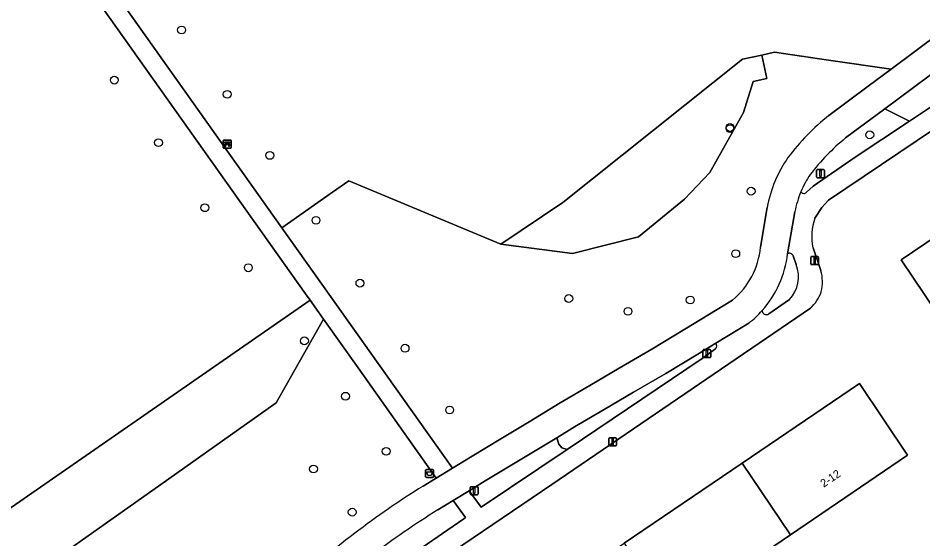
# Model space of a CAD drawing. Extents: x 157445 to 158888, y 383061 to 384688.
# Drawn here: x 157898.8 to 158011.8, y 383743.2 to 383808.2 of the extents above; entities that cross this region are included whole.
import ezdxf

# ---------------------------------------------------------------- set-up
doc = ezdxf.new("R2010")
doc.units = 0
for name, color, linetype in [('IMGEO_Afvalbak', 7, 'Continuous'), ('IMGEO_Bank', 7, 'Continuous'), ('IMGEO_Boom', 7, 'Continuous'), ('IMGEO_Erf', 7, 'Continuous'), ('IMGEO_Fietspad_gesloten', 7, 'Continuous'), ('IMGEO_Groenvoorziening', 7, 'Continuous'), ('IMGEO_Lichtmast', 7, 'Continuous'), ('IMGEO_Pand', 7, 'Continuous'), ('IMGEO_Pand_nummerreeks', 7, 'Continuous'), ('IMGEO_Voetpad_halfverhard', 7, 'Continuous')]:
    doc.layers.add(name, color=color, linetype=linetype)

msp = doc.modelspace()

# ---------------------------------------------------------------- linework, layer by layer
at = {"layer": 'IMGEO_Afvalbak'}
for p, q in [((157949.68, 383750.96), (157949.68, 383751.76)), ((157949.68, 383751.76), (157949.68, 383750.96)), ((157949.78, 383751.86), (157950.57, 383751.86)), ((157950.57, 383751.86), (157949.78, 383751.86)), ((157950.67, 383751.76), (157950.67, 383750.96)), ((157950.67, 383750.96), (157950.67, 383751.76)), ((157950.57, 383750.86), (157949.78, 383750.86)), ((157949.78, 383750.86), (157950.57, 383750.86))]:
    msp.add_line(p, q, dxfattribs=at)
msp.add_lwpolyline([(157949.82, 383751.57), (157950.52, 383751.57), (157950.37, 383751.1), (157949.97, 383751.1), (157949.82, 383751.57)], dxfattribs=at)
for centre, start, end in [((157949.78, 383751.76), 90, 180), ((157949.78, 383751.76), 90, 180), ((157950.57, 383751.76), 0, 90), ((157950.57, 383751.76), 360, 90), ((157949.78, 383750.96), 180, 270), ((157949.78, 383750.96), 180, 270), ((157950.57, 383750.96), 270, 0), ((157950.57, 383750.96), 270, 0)]:
    msp.add_arc(centre, 0.1, start, end, dxfattribs=at)
at = {"layer": 'IMGEO_Bank'}
for p, q in [((157924.41, 383792.04), (157924.41, 383792.88)), ((157924.41, 383792.88), (157924.41, 383792.04)), ((157924.48, 383792.97), (157925.32, 383792.97)), ((157925.32, 383792.97), (157924.48, 383792.97)), ((157925.4, 383792.89), (157925.4, 383792.05)), ((157925.4, 383792.05), (157925.4, 383792.89)), ((157925.33, 383791.97), (157924.49, 383791.97)), ((157924.49, 383791.97), (157925.33, 383791.97)), ((157924.71, 383792.47), (157924.71, 383792.58)), ((157925.1, 383792.36), (157924.71, 383792.36)), ((157925.05, 383792.58), (157924.76, 383792.58)), ((157924.76, 383792.58), (157924.76, 383792.47)), ((157924.76, 383792.47), (157925.05, 383792.47)), ((157925.05, 383792.47), (157925.05, 383792.58)), ((157925.1, 383792.58), (157925.1, 383792.47))]:
    msp.add_line(p, q, dxfattribs=at)
for points in [[(157924.65, 383792.36), (157924.51, 383792.36), (157924.62, 383792.47), (157924.71, 383792.47)], [(157924.71, 383792.58), (157924.62, 383792.58), (157924.62, 383792.75), (157925.19, 383792.75), (157925.19, 383792.58), (157925.1, 383792.58)], [(157924.7, 383792.36), (157924.7, 383792.15), (157924.66, 383792.15), (157924.66, 383792.36)], [(157925.1, 383792.47), (157925.19, 383792.47), (157925.3, 383792.36), (157925.16, 383792.36)], [(157925.15, 383792.36), (157925.15, 383792.15), (157925.11, 383792.15), (157925.11, 383792.36)]]:
    msp.add_lwpolyline(points, dxfattribs=at)
for centre, radius, start, end in [((157924.48, 383792.89), 0.0779, 92.4484, 184.2845), ((157924.48, 383792.89), 0.0779, 92.4484, 184.2845), ((157925.33, 383792.89), 0.0779, 2.4484, 94.2845), ((157925.33, 383792.89), 0.0779, 2.4484, 94.2845), ((157924.48, 383792.04), 0.0779, 182.4484, 274.2845), ((157924.48, 383792.04), 0.0779, 182.4484, 274.2845), ((157924.65, 383792.36), 0.00671, 2.8957, 87.1043), ((157924.71, 383792.36), 0.00671, 92.8957, 177.1043), ((157924.71, 383792.58), 0.00671, 2.8957, 87.1043), ((157924.71, 383792.47), 0.00671, 272.8957, 357.1043), ((157924.76, 383792.58), 0.00671, 92.8957, 177.1043), ((157924.76, 383792.47), 0.00671, 182.8957, 267.1043), ((157925.05, 383792.58), 0.00671, 2.8957, 87.1043), ((157925.05, 383792.47), 0.00671, 272.8957, 357.1043), ((157925.1, 383792.58), 0.00671, 92.8957, 177.1043), ((157925.1, 383792.47), 0.00671, 182.8957, 267.1043), ((157925.1, 383792.36), 0.00671, 2.8957, 87.1043), ((157925.16, 383792.36), 0.00671, 92.8957, 177.1043), ((157925.33, 383792.04), 0.0779, 272.4484, 4.2845), ((157925.33, 383792.04), 0.0779, 272.4484, 4.2845)]:
    msp.add_arc(centre, radius, start, end, dxfattribs=at)
at = {"layer": 'IMGEO_Boom'}
for centre in [(157919.2, 383806.7), (157910.8, 383800.44), (157924.9, 383798.67), (157987.69, 383794.53), (157987.69, 383794.39), (158005.14, 383793.61), (157916.31, 383792.64), (157930.22, 383791.05), (157990.32, 383786.58), (157922.11, 383784.52), (157935.98, 383782.95), (157988.4, 383778.79), (157927.53, 383777.03), (157941.47, 383775.11), (157967.55, 383773.19), (157982.72, 383773.01), (157974.94, 383771.59), (157934.54, 383767.91), (157947.11, 383766.99), (157939.67, 383761), (157952.68, 383759.29), (157944.75, 383754.13), (157935.67, 383751.93), (157940.51, 383746.54)]:
    msp.add_circle(centre, 0.489, dxfattribs=at)
at = {"layer": 'IMGEO_Erf'}
for points in [[(158015.06, 383769.11), (158009.05, 383778.04), (158023.72, 383787.93), (158038.43, 383797.85), (158053.11, 383807.74), (158059.13, 383798.82), (158044.45, 383788.92), (158029.74, 383779.01)], [(157965.89, 383723.81), (157959.82, 383732.77), (157974.48, 383742.69), (157989.2, 383752.66), (158003.86, 383762.58), (158009.87, 383753.66), (157995.23, 383743.72), (157980.54, 383733.75)]]:
    msp.add_lwpolyline(points, close=True, dxfattribs=at)
for points in [[(158024.3, 383801.81), (158000, 383785.45), (157999.15, 383784.53), (157998.29, 383783.2)], [(157998.05, 383779.53), (157999.04, 383776.67)], [(157997.72, 383771.99), (157965.42, 383750), (157950.71, 383739.99)]]:
    msp.add_lwpolyline(points, dxfattribs=at)
for centre, radius, start, end in [((158004.36, 383780.95), 6.47, 159.6574, 192.6688), ((157994.01, 383775.27), 5.22, 346.2888, 15.4975), ((157994.39, 383775.66), 4.96, 312.2197, 340.8918)]:
    msp.add_arc(centre, radius, start, end, dxfattribs=at)
at = {"layer": 'IMGEO_Fietspad_gesloten'}
for points in [[(158013.89, 383806.34), (158007.8, 383801.81), (158004.92, 383799.67), (158000.03, 383796.04)], [(158002.12, 383793.23), (158007.01, 383796.86), (158015.98, 383803.53)], [(157992.33, 383784.57), (157991.51, 383779.59)], [(157994.88, 383778.78), (157995.78, 383784.01)], [(157988.01, 383772.99), (157982.06, 383769.35), (157977.92, 383766.87), (157973.86, 383764.52), (157970.19, 383762.35), (157966.48, 383760.17), (157962.59, 383757.82), (157959.05, 383755.7), (157955.29, 383753.42), (157953.02, 383752.04), (157950.98, 383750.79), (157949.35, 383749.79)], [(157951.19, 383746.81), (157953.12, 383747.99), (157955.1, 383749.2), (157957.11, 383750.43), (157960.86, 383752.7), (157964.4, 383754.82), (157966.06, 383755.83), (157968.27, 383757.17), (157971.97, 383759.34), (157975.62, 383761.5), (157979.69, 383763.85), (157983.88, 383766.36), (157985.93, 383767.62), (157990.04, 383770.13)]]:
    msp.add_lwpolyline(points, dxfattribs=at)
for centre, radius, start, end in [((158018.86, 383772.59), 30.07, 128.7726, 142.785), ((158018.94, 383772.55), 26.65, 129.132, 142.82), ((158008.1, 383781.64), 16.04, 145.2695, 169.4764), ((158008.14, 383781.62), 12.59, 145.9866, 157.1941), ((158008.92, 383781.39), 13.4, 157.5985, 168.7371), ((157981.65, 383780.6), 9.91, 309.8678, 354.1487), ((157982.13, 383780.24), 12.83, 318.2123, 353.4888), ((157982.23, 383780.12), 12.68, 308.0057, 318.283), ((158002.15, 383664.27), 100.5, 121.6925, 127.5948), ((158002, 383664.49), 96.74, 121.6856, 127.6039), ((158010.5, 383651.88), 115.42, 127.1273, 132.8541)]:
    msp.add_arc(centre, radius, start, end, dxfattribs=at)
at = {"layer": 'IMGEO_Groenvoorziening'}
for points in [[(157947.81, 383908.45), (157904.24, 383852.49), (157897.07, 383843.39), (157895.49, 383841.38), (157893.13, 383838.5), (157893.58, 383835.72), (157894.56, 383834.4), (157906.36, 383817.74), (157931.74, 383782.01), (157938.04, 383786.45), (157940.08, 383787.89), (157959.05, 383779.97), (157966.82, 383785.16), (157989.25, 383803.05), (157991.64, 383803.57), (157993.23, 383803.91), (158000, 383802.93), (158007.8, 383801.81), (158013.89, 383806.34)], [(157874.04, 383842.42), (157871.01, 383843.07), (157845.04, 383847.43), (157846.95, 383865.51), (157846.51, 383865.55), (157845.36, 383867.13), (157844.48, 383869.82), (157844.01, 383877.86), (157841.91, 383862.89), (157840.6, 383852.7), (157835.43, 383801.71), (157833.4, 383784.91), (157830.98, 383767.08), (157846.43, 383747.46), (157867.23, 383761.67), (157884.44, 383737.79), (157935.24, 383772.99), (157934.69, 383773.78), (157900.3, 383822.21)], [(158000.03, 383796.04), (158004.92, 383799.67), (158007.8, 383801.81), (158000, 383802.93), (157993.23, 383803.91), (157991.64, 383803.57), (157992.27, 383800.63), (157990.57, 383800.27), (157989.36, 383796.4), (157985.18, 383788.91), (157982.02, 383785.6), (157976.24, 383780.91), (157968.01, 383778.81), (157959.05, 383779.97), (157940.08, 383787.89), (157938.04, 383786.45), (157931.74, 383782.01), (157953.02, 383752.04), (157955.29, 383753.42), (157959.05, 383755.7), (157962.59, 383757.82), (157966.48, 383760.17), (157970.19, 383762.35), (157973.86, 383764.52), (157977.92, 383766.87), (157982.06, 383769.35), (157988.01, 383772.99)], [(158015.98, 383803.53), (158007.01, 383796.86), (158010.08, 383795.31), (158017.73, 383800.38), (158020.24, 383802.04)], [(158010.08, 383795.31), (158007.01, 383796.86), (158002.12, 383793.23)], [(157997.24, 383786.47), (157998.08, 383787.23), (158003.3, 383790.82), (158010.08, 383795.31)], [(157991.51, 383779.59), (157992.33, 383784.57)], [(157995.95, 383777.43), (157995.56, 383778.54)], [(157839.99, 383696.7), (157885.52, 383728.99), (157898.79, 383709.99), (157901.95, 383712.88), (157889.49, 383730.85), (157916.62, 383750), (157931.02, 383760.17), (157936.92, 383770.63), (157935.24, 383772.99), (157884.44, 383737.79), (157867.23, 383761.67), (157846.43, 383747.46), (157844.87, 383746.4), (157827.34, 383734.43)], [(157992.53, 383771.28), (157995.1, 383773.07)], [(157949.35, 383749.79), (157950.98, 383750.79), (157941.24, 383764.54), (157936.92, 383770.63), (157931.02, 383760.17), (157916.62, 383750), (157889.49, 383730.85), (157901.95, 383712.88), (157898.79, 383709.99), (157885.52, 383728.99)], [(157985.93, 383767.62), (157983.88, 383766.36), (157979.69, 383763.85), (157975.62, 383761.5), (157971.97, 383759.34), (157968.27, 383757.17), (157966.06, 383755.83), (157966.29, 383755.03), (157966.67, 383754.58), (157967.34, 383754.36), (157984.2, 383765.7)], [(157984.2, 383765.7), (157985.75, 383766.82), (157985.88, 383766.91)], [(157948.58, 383741.68), (157954.43, 383745.69), (157954.67, 383745.86), (157953.12, 383747.99), (157951.19, 383746.81)]]:
    msp.add_lwpolyline(points, dxfattribs=at)
for points in [[(157990.57, 383800.27), (157992.27, 383800.63), (157991.64, 383803.57), (157989.25, 383803.05), (157966.82, 383785.16), (157959.05, 383779.97), (157968.01, 383778.81), (157976.24, 383780.91), (157982.02, 383785.6), (157985.18, 383788.91), (157989.36, 383796.4)], [(157967.34, 383754.36), (157966.67, 383754.58), (157966.29, 383755.03), (157966.06, 383755.83), (157964.4, 383754.82), (157960.86, 383752.7), (157957.11, 383750.43), (157955.1, 383749.2), (157956.61, 383747.15)]]:
    msp.add_lwpolyline(points, close=True, dxfattribs=at)
for centre, radius, start, end in [((158018.86, 383772.59), 30.07, 128.7726, 142.785), ((158018.94, 383772.55), 26.65, 129.132, 142.82), ((158008.1, 383781.64), 16.04, 145.2695, 169.4764), ((158008.14, 383781.62), 12.59, 145.9866, 157.1941), ((157996.9, 383786.74), 0.439, 213.8689, 321.9367), ((157981.65, 383780.6), 9.91, 309.8678, 354.1487), ((157982.13, 383780.24), 12.83, 318.2123, 353.4888), ((157995.1, 383778.34), 0.498, 24.11, 116.8601), ((157992.09, 383775.92), 4.15, 316.5475, 21.3583), ((157992.23, 383771.73), 0.539, 184.4033, 303.5143), ((157985.49, 383767.3), 0.543, 314.9194, 35.9845), ((158002.15, 383664.27), 100.5, 121.6925, 127.5948), ((158002, 383664.49), 96.74, 121.6856, 127.6039), ((158010.5, 383651.88), 115.42, 127.1273, 132.8541)]:
    msp.add_arc(centre, radius, start, end, dxfattribs=at)
at = {"layer": 'IMGEO_Lichtmast'}
for p, q in [((157998.48, 383788.37), (157998.48, 383789.17)), ((157998.48, 383789.17), (157998.48, 383788.37)), ((157998.58, 383789.27), (157999.37, 383789.27)), ((157999.37, 383789.27), (157998.58, 383789.27)), ((157999.37, 383788.27), (157998.58, 383788.27)), ((157998.58, 383788.27), (157999.37, 383788.27)), ((157999.47, 383789.17), (157999.47, 383788.37)), ((157999.47, 383788.37), (157999.47, 383789.17)), ((157997.76, 383777.52), (157997.76, 383778.32)), ((157997.76, 383778.32), (157997.76, 383777.52)), ((157997.86, 383778.42), (157998.65, 383778.42)), ((157998.65, 383778.42), (157997.86, 383778.42)), ((157998.75, 383778.32), (157998.75, 383777.52)), ((157998.75, 383777.52), (157998.75, 383778.32)), ((157998.65, 383777.42), (157997.86, 383777.42)), ((157997.86, 383777.42), (157998.65, 383777.42)), ((157984.39, 383766.82), (157985.18, 383766.82)), ((157985.18, 383766.82), (157984.39, 383766.82)), ((157984.29, 383765.92), (157984.29, 383766.72)), ((157984.29, 383766.72), (157984.29, 383765.92)), ((157985.18, 383765.82), (157984.39, 383765.82)), ((157984.39, 383765.82), (157985.18, 383765.82)), ((157985.28, 383766.72), (157985.28, 383765.92)), ((157985.28, 383765.92), (157985.28, 383766.72)), ((157972.54, 383754.91), (157972.54, 383755.71)), ((157972.54, 383755.71), (157972.54, 383754.91)), ((157972.64, 383755.81), (157973.43, 383755.81)), ((157973.43, 383755.81), (157972.64, 383755.81)), ((157973.53, 383755.71), (157973.53, 383754.91)), ((157973.53, 383754.91), (157973.53, 383755.71)), ((157973.43, 383754.81), (157972.64, 383754.81)), ((157972.64, 383754.81), (157973.43, 383754.81)), ((157955.25, 383748.82), (157955.25, 383749.62)), ((157955.25, 383749.62), (157955.25, 383748.82)), ((157955.35, 383749.72), (157956.14, 383749.72)), ((157956.14, 383749.72), (157955.35, 383749.72)), ((157956.14, 383748.72), (157955.35, 383748.72)), ((157955.35, 383748.72), (157956.14, 383748.72)), ((157956.24, 383749.62), (157956.24, 383748.82)), ((157956.24, 383748.82), (157956.24, 383749.62))]:
    msp.add_line(p, q, dxfattribs=at)
for points in [[(157998.9, 383789.15), (157999.05, 383789.15), (157999.05, 383788.4), (157998.9, 383788.4), (157998.9, 383789.15)], [(157998.18, 383778.3), (157998.33, 383778.3), (157998.33, 383777.55), (157998.18, 383777.55), (157998.18, 383778.3)], [(157984.71, 383766.7), (157984.86, 383766.7), (157984.86, 383765.95), (157984.71, 383765.95), (157984.71, 383766.7)], [(157972.96, 383755.69), (157973.11, 383755.69), (157973.11, 383754.94), (157972.96, 383754.94), (157972.96, 383755.69)], [(157955.67, 383749.6), (157955.82, 383749.6), (157955.82, 383748.85), (157955.67, 383748.85), (157955.67, 383749.6)]]:
    msp.add_lwpolyline(points, dxfattribs=at)
for centre, start, end in [((157998.58, 383789.17), 90, 180), ((157998.58, 383789.17), 90, 180), ((157998.58, 383788.37), 180, 270), ((157998.58, 383788.37), 180, 270), ((157999.37, 383789.17), 0, 90), ((157999.37, 383789.17), 360, 90), ((157999.37, 383788.37), 270, 0), ((157999.37, 383788.37), 270, 0), ((157997.86, 383778.32), 90, 180), ((157997.86, 383778.32), 90, 180), ((157998.65, 383778.32), 0, 90), ((157998.65, 383778.32), 360, 90), ((157997.86, 383777.52), 180, 270), ((157997.86, 383777.52), 180, 270), ((157998.65, 383777.52), 270, 0), ((157998.65, 383777.52), 270, 0), ((157984.39, 383766.72), 90, 180), ((157984.39, 383766.72), 90, 180), ((157985.18, 383766.72), 0, 90), ((157985.18, 383766.72), 360, 90), ((157984.39, 383765.92), 180, 270), ((157984.39, 383765.92), 180, 270), ((157985.18, 383765.92), 270, 0), ((157985.18, 383765.92), 270, 0), ((157972.64, 383755.71), 90, 180), ((157972.64, 383755.71), 90, 180), ((157973.43, 383755.71), 0, 90), ((157973.43, 383755.71), 360, 90), ((157972.64, 383754.91), 180, 270), ((157972.64, 383754.91), 180, 270), ((157973.43, 383754.91), 270, 0), ((157973.43, 383754.91), 270, 0), ((157955.35, 383749.62), 90, 180), ((157955.35, 383749.62), 90, 180), ((157955.35, 383748.82), 180, 270), ((157955.35, 383748.82), 180, 270), ((157956.14, 383749.62), 0, 90), ((157956.14, 383749.62), 360, 90), ((157956.14, 383748.82), 270, 0), ((157956.14, 383748.82), 270, 0)]:
    msp.add_arc(centre, 0.1, start, end, dxfattribs=at)
at = {"layer": 'IMGEO_Pand'}
for points in [[(158029.74, 383779.01), (158023.72, 383787.93), (158009.05, 383778.04), (158015.06, 383769.11)], [(157995.23, 383743.72), (158009.87, 383753.66), (158003.86, 383762.58), (157989.2, 383752.66)], [(157980.54, 383733.75), (157995.23, 383743.72), (157989.2, 383752.66), (157974.48, 383742.69)]]:
    msp.add_lwpolyline(points, close=True, dxfattribs=at)
at = {"layer": 'IMGEO_Voetpad_halfverhard'}
for points in [[(157900.3, 383822.21), (157934.69, 383773.78), (157935.24, 383772.99), (157936.92, 383770.63), (157941.24, 383764.54), (157950.98, 383750.79), (157953.02, 383752.04), (157931.74, 383782.01), (157906.36, 383817.74)], [(158020.24, 383802.04), (158017.73, 383800.38), (158010.08, 383795.31), (158003.3, 383790.82), (157998.08, 383787.23), (157997.24, 383786.47)], [(157998.29, 383783.2), (157999.15, 383784.53), (158000, 383785.45), (158024.3, 383801.81)], [(157995.78, 383784.01), (157994.88, 383778.78)], [(157999.04, 383776.67), (157998.05, 383779.53)], [(157995.56, 383778.54), (157995.95, 383777.43)], [(157995.1, 383773.07), (157992.53, 383771.28)], [(157950.71, 383739.99), (157965.42, 383750), (157997.72, 383771.99)], [(157990.04, 383770.13), (157985.93, 383767.62)], [(157985.88, 383766.91), (157985.75, 383766.82), (157984.2, 383765.7), (157967.34, 383754.36), (157956.61, 383747.15), (157955.1, 383749.2), (157953.12, 383747.99), (157954.67, 383745.86), (157954.43, 383745.69), (157948.58, 383741.68)]]:
    msp.add_lwpolyline(points, dxfattribs=at)
for centre, radius, start, end in [((158008.92, 383781.39), 13.4, 157.5985, 168.7371), ((157996.9, 383786.74), 0.439, 213.8689, 321.9367), ((158004.36, 383780.95), 6.47, 159.6574, 192.6688), ((157995.1, 383778.34), 0.498, 24.11, 116.8601), ((157992.09, 383775.92), 4.15, 316.5475, 21.3583), ((157994.01, 383775.27), 5.22, 346.2888, 15.4975), ((157994.39, 383775.66), 4.96, 312.2197, 340.8918), ((157982.23, 383780.12), 12.68, 308.0057, 318.283), ((157992.23, 383771.73), 0.539, 184.4033, 303.5143), ((157985.49, 383767.3), 0.543, 314.9194, 35.9845)]:
    msp.add_arc(centre, radius, start, end, dxfattribs=at)

# ---------------------------------------------------------------- texts
at = {"layer": 'IMGEO_Pand_nummerreeks'}
msp.add_text('2-12', height=1, rotation=34.157, dxfattribs=at).set_placement((157999.39, 383749.59))

doc.saveas('drawing.dxf')
